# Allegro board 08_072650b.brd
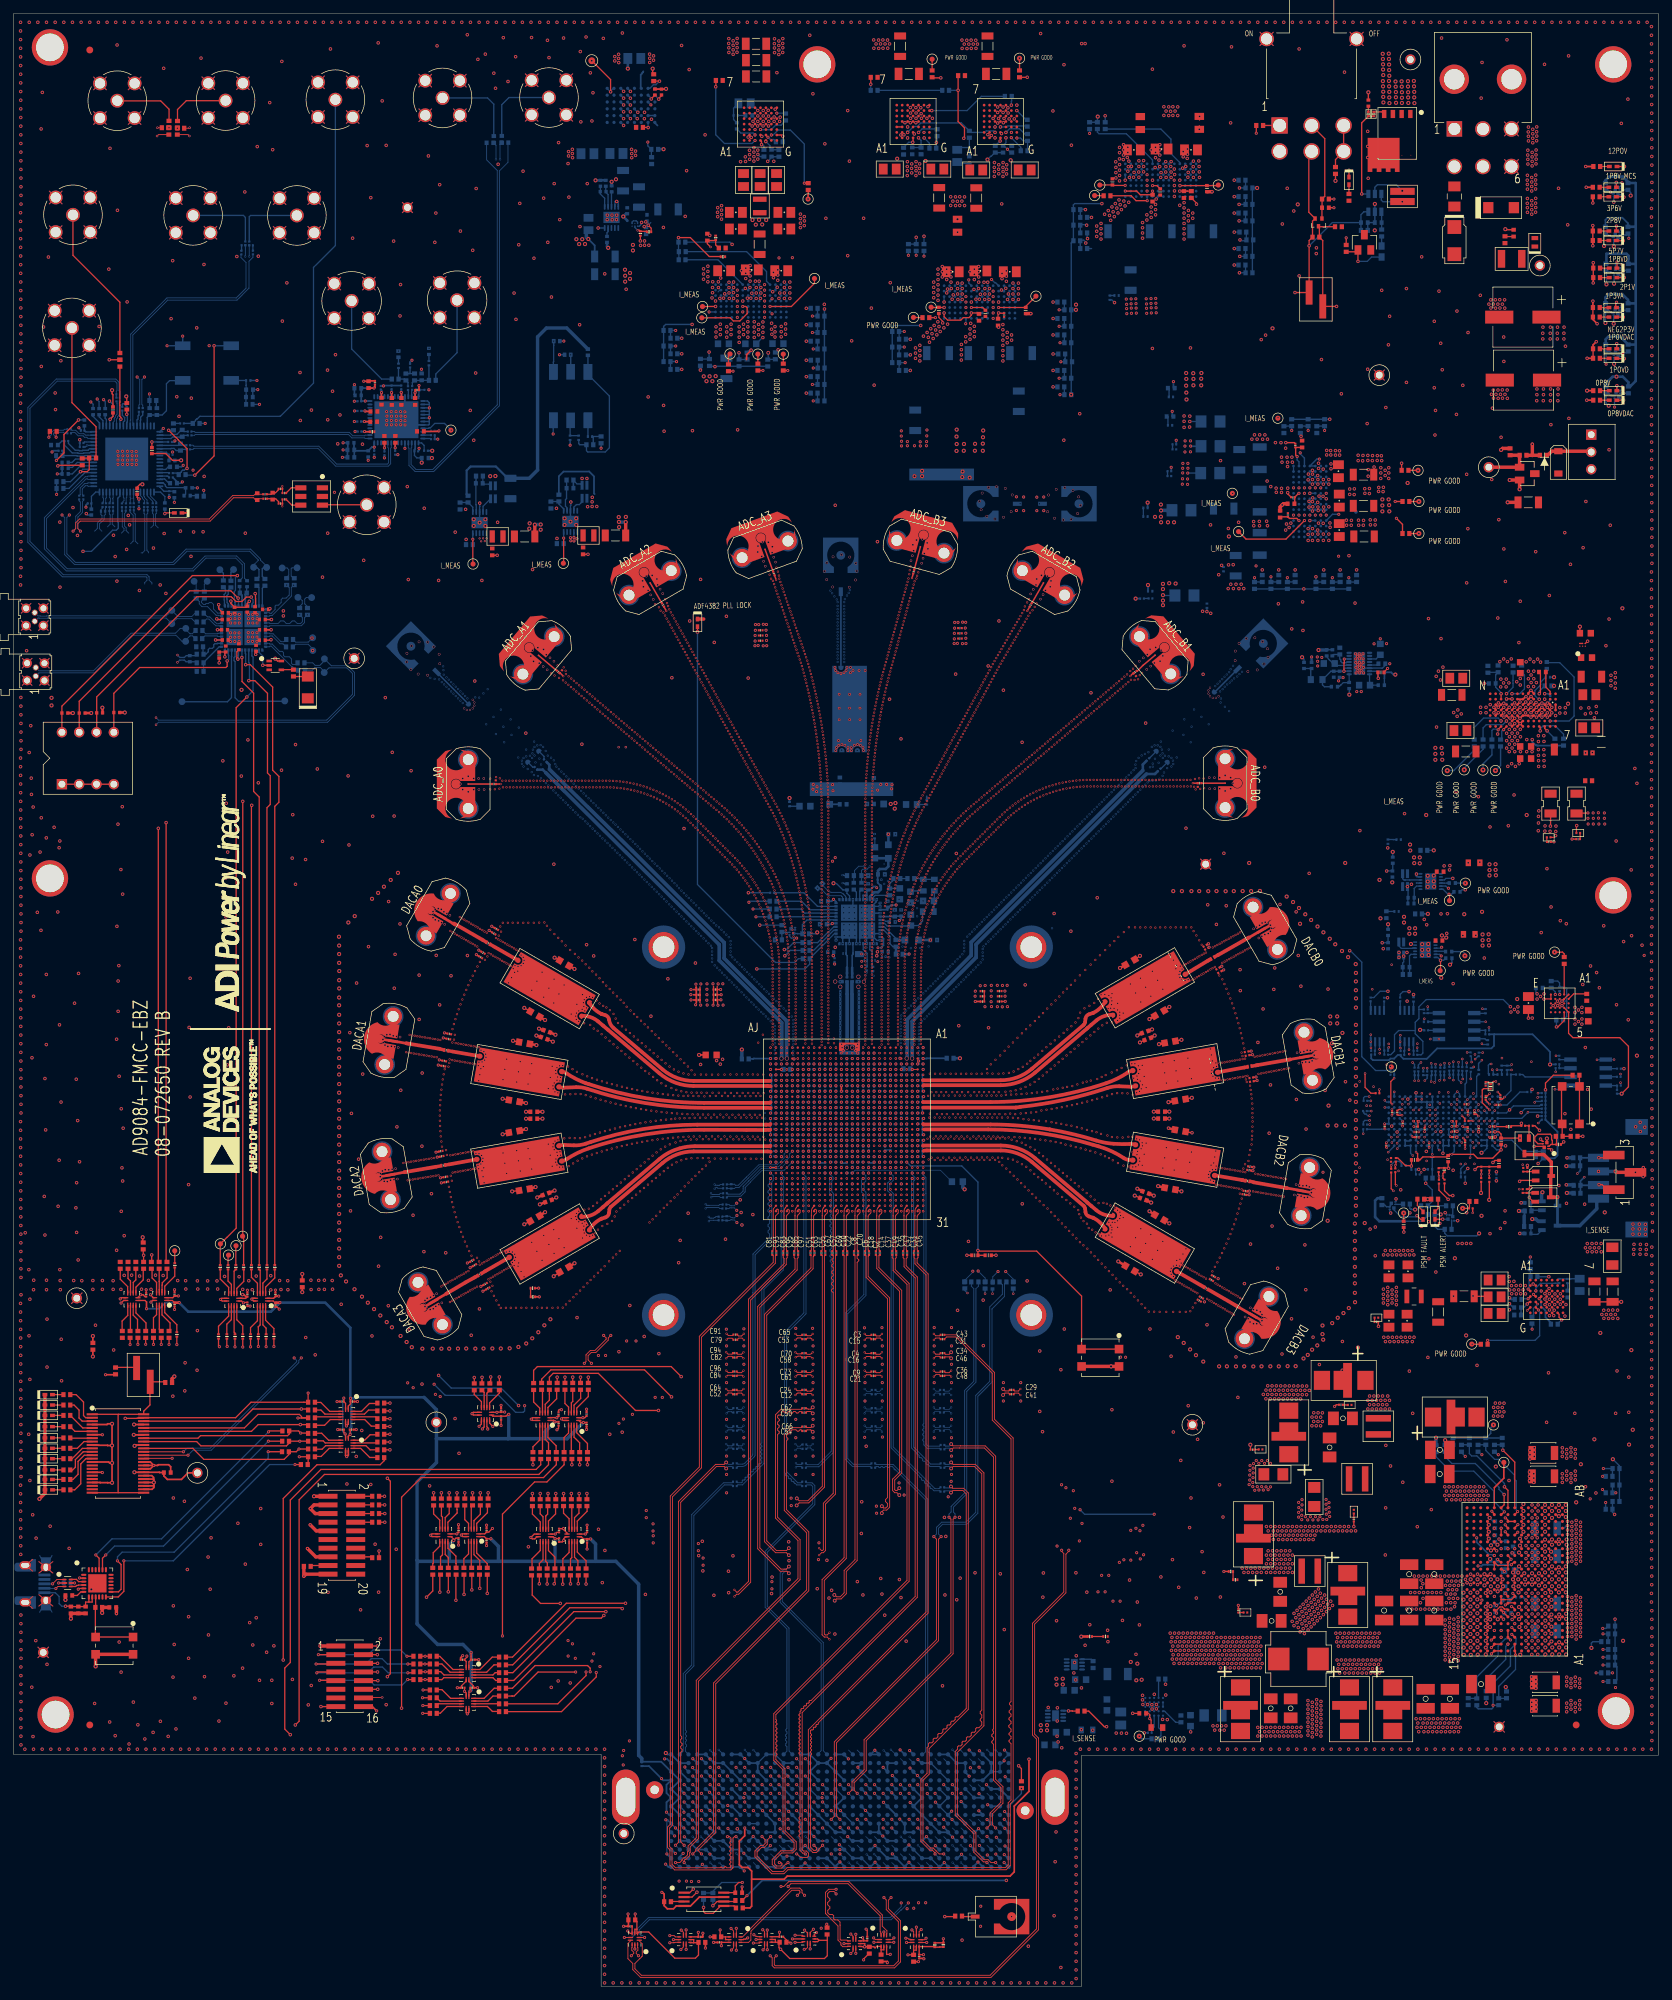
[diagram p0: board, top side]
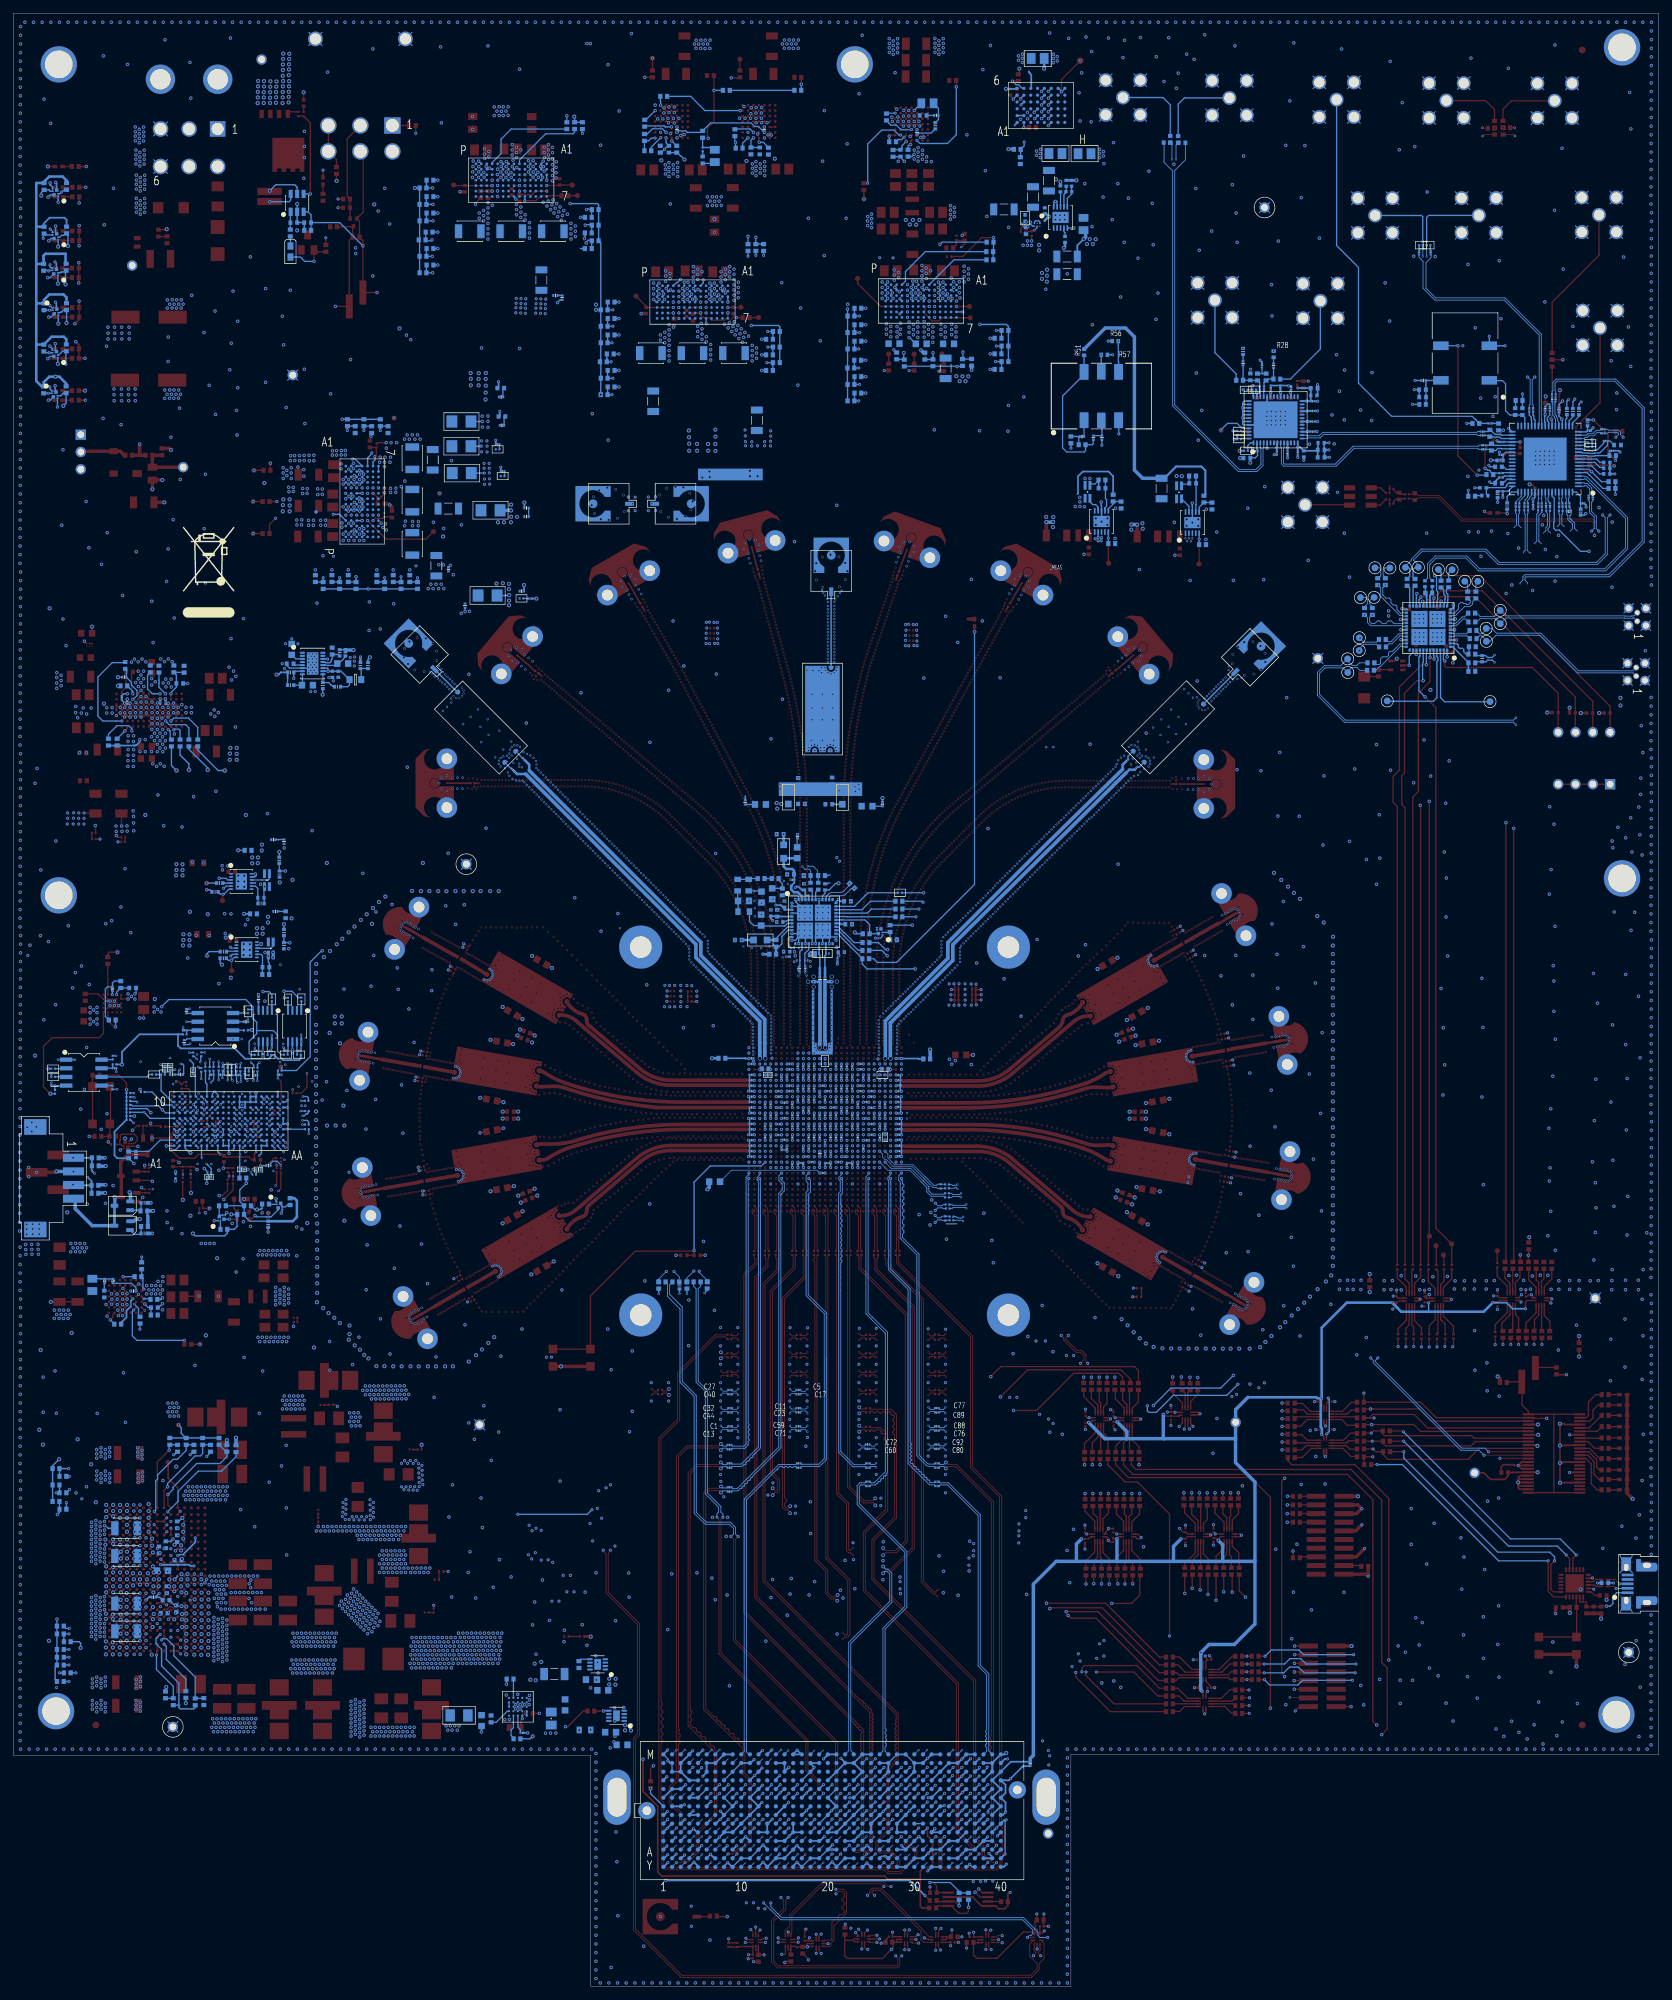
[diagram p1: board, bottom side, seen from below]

Outline 241.43 x 289.43 mm; copper layers: TOP, L2_GROUND, L3_SIGNAL, L4_GROUND, L5_MIXED, L6_GROUND, L7_POWER, L8_GROUND, L9_POWER, L10_GROUND, L11_POWER, L12_GROUND, L13_GROUND, L14_POWER, L15_GROUND, L16_POWER, L17_GROUND, L18_POWER, L19_GROUND, L20_POWER, L21_GROUND, L22_MIXED, L23_GROUND, L24_SIGNAL, L25_GROUND, BOTTOM. Coordinates in mm from the lower left corner of the outline.
Outline path: 0,289.43 0,34.04 86.23,34.04 86.23,0 156.72,0 156.72,33.91 241.43,33.91 241.43,289.43 0,289.43

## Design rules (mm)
constraint set DEFAULT: min track width 0.191
net group 4382_CLK_P_N: nets UNNAMED_9_CAP_I76_N2 UNNAMED_9_CAP_I78_N2
net group ADF4382_OUT: nets ADF4382_OUTN ADF4382_OUTP
net group ADS10_REFCLK: nets ADS10_REFCLK_N ADS10_REFCLK_P
net group AION_REFIN_N: nets AION_REFIN_N REFIN_DUT_N
net group AION_REFIN_P: nets AION_REFIN_P REFIN_DUT_P
net group APOLLO_SYSREF_N: nets APOLLO_SYSREF_N BSYNC5_N
net group APOLLO_SYSREF_P: nets APOLLO_SYSREF_P BSYNC5_P
net group ARTEMIS_REFIN: nets ARTEMIS_REFIN_N ARTEMIS_REFIN_P
net group ARTEMIS_SYNC: nets ARTEMIS_SYNC_N ARTEMIS_SYNC_P
net group BSYNC1_N: nets BSYNC1_N UNNAMED_52_CN2P4GNDV2_I39_N1
net group BSYNC1_P: nets BSYNC1_P UNNAMED_52_CN2P4GNDV2_I39_N2
net group BSYNC2_N: nets BSYNC2_N UNNAMED_52_CN2P4GNDV2_I35_N1
net group BSYNC2_P: nets BSYNC2_P UNNAMED_52_CN2P4GNDV2_I35_N2
net group BSYNC3_N: nets BSYNC3_N UNNAMED_52_NCTESTPAD_I168_N1
net group BSYNC3_P: nets BSYNC3_P UNNAMED_52_NCTESTPAD_I164_N1
net group BSYNC4_N: nets BSYNC4_N UNNAMED_52_NCTESTPAD_I177_N1
net group BSYNC4_P: nets BSYNC4_P UNNAMED_52_NCTESTPAD_I165_N1
net group BSYNC6_N: nets BSYNC6_N UNNAMED_52_NCTESTPAD_I170_N1
net group BSYNC6_P: nets BSYNC6_P UNNAMED_52_NCTESTPAD_I167_N1
net group BSYNC7_N: nets BSYNC7_N UNNAMED_52_NCTESTPAD_I176_N1
net group BSYNC7_P: nets BSYNC7_P UNNAMED_52_NCTESTPAD_I175_N1
net group CLKA: nets CLKA_N CLKA_P
net group CLKB: nets CLKB_N CLKB_P
net group CLKC: nets CLKC_N CLKC_P
net group DP1: nets UNNAMED_11_ADHMC7044_I155_CLKOUT0 UNNAMED_11_ADHMC7044_I155_CLKOUT0N
net group DP2: nets CLK_M2C_N_0 CLK_M2C_P_0
net group DP3: nets CLK_M2C_N_1 CLK_M2C_P_1
net group DP4: nets HSCI_CKO_N_FMC HSCI_CKO_P_FMC
net group DP5: nets HSCI_DIN_N_FMC HSCI_DIN_P_FMC
net group DP6: nets HSCI_DO_N_FMC HSCI_DO_P_FMC
net group DP7: nets SYNCINB_A0_N_FMC SYNCINB_A0_P_FMC
net group DP8: nets SYNCINB_A1_N_FMC SYNCINB_A1_P_FMC
net group DP9: nets SYNCINB_B0_N_FMC SYNCINB_B0_P_FMC
net group DP10: nets SYNCINB_B1_N_FMC SYNCINB_B1_P_FMC
net group DP11: nets SYSREF_A_N_FMC SYSREF_A_P_FMC
net group DP12: nets SYSREF_B_N_FMC SYSREF_B_P_FMC
net group DP13: nets SYSREF_N_FMC SYSREF_P_FMC
net group DP14: nets SYNCINB_A0_N_GPIO_FMC SYNCINB_A0_P_GPIO_FMC
net group DP15: nets SYNCINB_A1_N_GPIO_FMC SYNCINB_A1_P_GPIO_FMC
net group DP16: nets SYNCOUTB_A0_N_FMC SYNCOUTB_A0_P_FMC
net group DP17: nets SYNCOUTB_A1_N_FMC SYNCOUTB_A1_P_FMC
net group DP18: nets SYNCOUTB_B0_N_FMC SYNCOUTB_B0_P_FMC
net group DP19: nets SYNCOUTB_B1_N_FMC SYNCOUTB_B1_P_FMC
net group DP20: nets SYNCINB_B0_N_GPIO_FMC SYNCINB_B0_P_GPIO_FMC
net group DP21: nets SYNCOUTB_A0_N_GPIO_FMC SYNCOUTB_A0_P_GPIO_FMC
net group DP22: nets SYNCOUTB_A1_N_GPIO_FMC SYNCOUTB_A1_P_GPIO_FMC
net group DP23: nets SYNCINB_B1_N_GPIO_FMC SYNCINB_B1_P_GPIO_FMC
net group DP24: nets SYNCOUTB_B0_N_GPIO_FMC SYNCOUTB_B0_P_GPIO_FMC
net group DP25: nets SYNCOUTB_B1_N_GPIO_FMC SYNCOUTB_B1_P_GPIO_FMC
net group DP26: nets UNNAMED_36_CAP_I371_N1 UNNAMED_36_CAP_I372_N1
net group DP27: nets UNNAMED_11_ADHMC7044_I155_CLKOUT6 UNNAMED_11_ADHMC7044_I155_CLKOUT6N
net group FPGA_REFCLK_0: nets FPGA_REFCLK_0_N FPGA_REFCLK_0_P
net group FPGA_REFCLK_1: nets FPGA_REFCLK_1_N FPGA_REFCLK_1_P
net group FPGA_REFCLK_2: nets FPGA_REFCLK_2_N FPGA_REFCLK_2_P
net group FPGA_REFCLK_3: nets FPGA_REFCLK_3_N FPGA_REFCLK_3_P
net group FPGA_REFCLK_4: nets FPGA_REFCLK_4_N FPGA_REFCLK_4_P
net group FPGA_REFCLK_5: nets FPGA_REFCLK_5_N FPGA_REFCLK_5_P
net group HMC7044_CLK0: nets HMC7044_CLK0_N HMC7044_CLK0_P
net group HMC7044_CLK2: nets HMC7044_CLK2_N HMC7044_CLK2_P
net group HMC7044_CLK5: nets HMC7044_CLK5_N HMC7044_CLK5_P
net group HMC7044_CLK8: nets HMC7044_CLK8_N HMC7044_CLK8_P
net group HMC7044_CLK9: nets HMC7044_CLK9_N HMC7044_CLK9_P
net group HMC7044_CLK10: nets HMC7044_CLK10_N HMC7044_CLK10_P
net group HMC7044_CLK11: nets HMC7044_CLK11_N HMC7044_CLK11_P
net group HMC7044_CLK12: nets HMC7044_CLK12_N HMC7044_CLK12_P
net group HMC7044_CLK13: nets HMC7044_CLK13_N HMC7044_CLK13_P
net group HMC7044_FIN: nets HMC7044_FIN_N HMC7044_FIN_P
net group HMC7044_REFIN: nets HMC7044_REFIN_N HMC7044_REFIN_P
net group HSCI-CLKIN_P_N_FMC: nets HSCI_CKIN_N_FMC HSCI_CKIN_P_FMC
net group HSCI_CKIN: nets HSCI_CKIN_N HSCI_CKIN_P
net group HSCI_CKO: nets HSCI_CKO_N HSCI_CKO_P
net group HSCI_DIN: nets HSCI_DIN_N HSCI_DIN_P
net group HSCI_DO: nets HSCI_DO_N HSCI_DO_P
net group REFCLK: nets REFCLK_N REFCLK_P
net group RFOUT-N-P: nets UNNAMED_36_CAP_I396_N1 UNNAMED_36_CAP_I397_N1
net group SRXA_0: nets SRXA_0N SRXA_0P
net group SRXA_1: nets SRXA_1N SRXA_1P
net group SRXA_2: nets SRXA_2N SRXA_2P
net group SRXA_3: nets SRXA_3N SRXA_3P
net group SRXA_4: nets SRXA_4N SRXA_4P
net group SRXA_5: nets SRXA_5N SRXA_5P
net group SRXA_6: nets SRXA_6N SRXA_6P
net group SRXA_7: nets SRXA_7N SRXA_7P
net group SRXA_8: nets SRXA_8N SRXA_8P
net group SRXA_9: nets SRXA_9N SRXA_9P
net group SRXA_10: nets SRXA_10N SRXA_10P
net group SRXA_11: nets SRXA_11N SRXA_11P
net group SRXA_FMC_0: nets SRXA_0N_FMC SRXA_0P_FMC
net group SRXA_FMC_1: nets SRXA_1N_FMC SRXA_1P_FMC
net group SRXA_FMC_2: nets SRXA_2N_FMC SRXA_2P_FMC
net group SRXA_FMC_3: nets SRXA_3N_FMC SRXA_3P_FMC
net group SRXA_FMC_4: nets SRXA_4N_FMC SRXA_4P_FMC
net group SRXA_FMC_5: nets SRXA_5N_FMC SRXA_5P_FMC
net group SRXA_FMC_6: nets SRXA_6N_FMC SRXA_6P_FMC
net group SRXA_FMC_7: nets SRXA_7N_FMC SRXA_7P_FMC
net group SRXA_FMC_8: nets SRXA_8N_FMC SRXA_8P_FMC
net group SRXA_FMC_9: nets SRXA_9N_FMC SRXA_9P_FMC
net group SRXA_FMC_10: nets SRXA_10N_FMC SRXA_10P_FMC
net group SRXA_FMC_11: nets SRXA_11N_FMC SRXA_11P_FMC
net group SRXB_0: nets SRXB_0N SRXB_0P
net group SRXB_1: nets SRXB_1N SRXB_1P
net group SRXB_2: nets SRXB_2N SRXB_2P
net group SRXB_3: nets SRXB_3N SRXB_3P
net group SRXB_4: nets SRXB_4N SRXB_4P
net group SRXB_5: nets SRXB_5N SRXB_5P
net group SRXB_6: nets SRXB_6N SRXB_6P
net group SRXB_7: nets SRXB_7N SRXB_7P
net group SRXB_8: nets SRXB_8N SRXB_8P
net group SRXB_9: nets SRXB_9N SRXB_9P
net group SRXB_10: nets SRXB_10N SRXB_10P
net group SRXB_11: nets SRXB_11N SRXB_11P
net group SRXB_FMC_0: nets SRXB_0N_FMC SRXB_0P_FMC
net group SRXB_FMC_1: nets SRXB_1N_FMC SRXB_1P_FMC
net group SRXB_FMC_2: nets SRXB_2N_FMC SRXB_2P_FMC
net group SRXB_FMC_3: nets SRXB_3N_FMC SRXB_3P_FMC
net group SRXB_FMC_4: nets SRXB_4N_FMC SRXB_4P_FMC
net group SRXB_FMC_5: nets SRXB_5N_FMC SRXB_5P_FMC
net group SRXB_FMC_6: nets SRXB_6N_FMC SRXB_6P_FMC
net group SRXB_FMC_7: nets SRXB_7N_FMC SRXB_7P_FMC
net group SRXB_FMC_8: nets SRXB_8N_FMC SRXB_8P_FMC
net group SRXB_FMC_9: nets SRXB_9N_FMC SRXB_9P_FMC
net group SRXB_FMC_10: nets SRXB_10N_FMC SRXB_10P_FMC
net group SRXB_FMC_11: nets SRXB_11N_FMC SRXB_11P_FMC
net group STXA_0: nets STXA_0N STXA_0P
net group STXA_1: nets STXA_1N STXA_1P
net group STXA_2: nets STXA_2N STXA_2P
net group STXA_3: nets STXA_3N STXA_3P
net group STXA_4: nets STXA_4N STXA_4P
net group STXA_5: nets STXA_5N STXA_5P
net group STXA_6: nets STXA_6N STXA_6P
net group STXA_7: nets STXA_7N STXA_7P
net group STXA_8: nets STXA_8N STXA_8P
net group STXA_9: nets STXA_9N STXA_9P
net group STXA_10: nets STXA_10N STXA_10P
net group STXA_11: nets STXA_11N STXA_11P
net group STXA_FMC_0: nets STXA_0N_FMC STXA_0P_FMC
net group STXA_FMC_1: nets STXA_1N_FMC STXA_1P_FMC
net group STXA_FMC_2: nets STXA_2N_FMC STXA_2P_FMC
net group STXA_FMC_3: nets STXA_3N_FMC STXA_3P_FMC
net group STXA_FMC_4: nets STXA_4N_FMC STXA_4P_FMC
net group STXA_FMC_5: nets STXA_5N_FMC STXA_5P_FMC
net group STXA_FMC_6: nets STXA_6N_FMC STXA_6P_FMC
net group STXA_FMC_7: nets STXA_7N_FMC STXA_7P_FMC
net group STXA_FMC_8: nets STXA_8N_FMC STXA_8P_FMC
net group STXA_FMC_9: nets STXA_9N_FMC STXA_9P_FMC
net group STXA_FMC_10: nets STXA_10N_FMC STXA_10P_FMC
net group STXA_FMC_11: nets STXA_11N_FMC STXA_11P_FMC
net group STXB_0: nets STXB_0N STXB_0P
net group STXB_1: nets STXB_1N STXB_1P
net group STXB_2: nets STXB_2N STXB_2P
net group STXB_3: nets STXB_3N STXB_3P
net group STXB_4: nets STXB_4N STXB_4P
net group STXB_5: nets STXB_5N STXB_5P
net group STXB_6: nets STXB_6N STXB_6P
net group STXB_7: nets STXB_7N STXB_7P
net group STXB_8: nets STXB_8N STXB_8P
net group STXB_9: nets STXB_9N STXB_9P
net group STXB_10: nets STXB_10N STXB_10P
net group STXB_11: nets STXB_11N STXB_11P
net group STXB_FMC_0: nets STXB_0N_FMC STXB_0P_FMC
net group STXB_FMC_1: nets STXB_1N_FMC STXB_1P_FMC
net group STXB_FMC_2: nets STXB_2N_FMC STXB_2P_FMC
net group STXB_FMC_3: nets STXB_3N_FMC STXB_3P_FMC
net group STXB_FMC_4: nets STXB_4N_FMC STXB_4P_FMC
net group STXB_FMC_5: nets STXB_5N_FMC STXB_5P_FMC
net group STXB_FMC_6: nets STXB_6N_FMC STXB_6P_FMC
net group STXB_FMC_7: nets STXB_7N_FMC STXB_7P_FMC
net group STXB_FMC_8: nets STXB_8N_FMC STXB_8P_FMC
net group STXB_FMC_9: nets STXB_9N_FMC STXB_9P_FMC
net group STXB_FMC_10: nets STXB_10N_FMC STXB_10P_FMC
net group STXB_FMC_11: nets STXB_11N_FMC STXB_11P_FMC
net group SYNCINB_A0: nets SYNCINB_A0_N SYNCINB_A0_P
net group SYNCINB_A1: nets SYNCINB_A1_N SYNCINB_A1_P
net group SYNCINB_B0: nets SYNCINB_B0_N SYNCINB_B0_P
net group SYNCINB_B1: nets SYNCINB_B1_N SYNCINB_B1_P
net group SYNCOUTB_A0: nets SYNCOUTB_A0_N SYNCOUTB_A0_P
net group SYNCOUTB_A1: nets SYNCOUTB_A1_N SYNCOUTB_A1_P
net group SYNCOUTB_B0: nets SYNCOUTB_B0_N SYNCOUTB_B0_P
net group SYNCOUTB_B1: nets SYNCOUTB_B1_N SYNCOUTB_B1_P
net group SYSREF: nets SYSREF_N SYSREF_P
net group SYSREF_A: nets SYSREF_A_N SYSREF_A_P
net group SYSREF_B: nets SYSREF_B_N SYSREF_B_P
net group SYSREF_IN_N_FMC: nets BSYNC8_N SYSREF_IN_N_FMC
net group SYSREF_IN_P_FMC: nets BSYNC8_P SYSREF_IN_P_FMC
net group SYSREF_OUT_N_FMC: nets BSYNC9_N SYSREF_OUT_N_FMC
net group SYSREF_OUT_P_FMC: nets BSYNC9_P SYSREF_OUT_P_FMC
net group UNNAMED_29_ADF4382_I312_SYNC: nets UNNAMED_36_ADF4382_I312_SYNCN UNNAMED_36_ADF4382_I312_SYNCP
net group USB_D: nets USB_DN USB_DP
nets with their own width: min track width 0.108; nets UNNAMED_15_ADLTM4681_I3_PGOOD0 UNNAMED_41_ADLTM4709_I15_VO20 UNNAMED_41_ADLTM4709_I15_VO32
nets with their own width: min track width 0.133; nets UNNAMED_15_ADLTM4681_I3_PGOOD2
nets with their own width: min track width 0.178; nets DGND FMC_3P3V FMC_VADJ VDDD_1P8
nets with their own width: min track width 0.191; nets UNNAMED_15_ADLTM4681_I3_SDA01 VNEGM1P0_ADC

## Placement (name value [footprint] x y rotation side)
A1  LT1990IMS8-10#PBF  [MSOP8]  200.18 140.89 0 bottom
A2  LT1990IMS8-10#PBF  [MSOP8]  204.5 140.89 0 bottom
A3  LT1990HS8#PBF  [SO8NB-5]  211.81 140.89 90 bottom
A4  LT1990HS8#PBF  [SO8NB-5]  231.11 134.06 270 bottom
ADC_A0  SF1521-60070-1S  [CNAMPHENOLSF1521-60070-XS#2]  66.73 176.4 90 top
ADC_A1  SF1521-60070-1S  [CNAMPHENOLSF1521-60070-XS#2]  77.05 195.28 50 top
ADC_A2  SF1521-60070-1S  [CNAMPHENOLSF1521-60070-XS#2]  93.43 205.91 30 top
ADC_A3  SF1521-60070-1S  [CNAMPHENOLSF1521-60070-XS#2]  110.3 210.83 20 top
ADC_B0  SF1521-60070-1S  [CNAMPHENOLSF1521-60070-XS#2]  177.83 176.53 270 top
ADC_B1  SF1521-60070-1S  [CNAMPHENOLSF1521-60070-XS#2]  167.55 195.3 310 top
ADC_B2  SF1521-60070-1S  [CNAMPHENOLSF1521-60070-XS#2]  151.17 205.91 330 top
ADC_B3  SF1521-60070-1S  [CNAMPHENOLSF1521-60070-XS#2]  133.1 211.21 345 top
BUFDIS  TMM-102-01-G-S-SM  [CNSAMTECTMM-102-01-G-S-SM]  19.05 89.71 0 top
C1  0.1uF  [C0201]  136.27 82.17 180 bottom
C1WA  1uF  [C0603]  80.84 150.12 150 top
C1WB  1uF  [C0603]  168.2 142.78 30 top
C1XA  1uF  [C0603]  74.98 138.41 170 top
C1XB  1uF  [C0603]  169.75 138.55 10 top
C1YA  1uF  [C0603]  73.48 125.4 190 top
C1YB  1uF  [C0603]  171.24 125.54 350 top
C1ZA  1uF  [C0603]  76.52 112.66 210 top
C1ZB  1uF  [C0603]  168.2 112.8 330 top
C2  0.1uF  [C0201]  126.57 107.6 90 top
C2WA  1uF  [C0603]  76.52 142.64 150 top
C2WB  1uF  [C0603]  163.89 150.26 30 top
C2XA  1uF  [C0603]  73.48 129.91 170 top
C2XB  1uF  [C0603]  171.24 130.05 10 top
C2YA  1uF  [C0603]  74.98 116.89 190 top
C2YB  1uF  [C0603]  169.75 117.03 350 top
C2ZA  1uF  [C0603]  80.84 105.18 210 top
C2ZB  1uF  [C0603]  163.89 105.32 330 top
C3  0.1uF  [C0201]  126.19 95.59 180 top
C3WA  0.1uF  [C0201]  70.49 154.48 150 top
C3WB  0.1uF  [C0201]  174.9 152.68 30 top
C3XA  0.1uF  [C0201]  63.82 138.99 170 top
C3XB  0.1uF  [C0201]  181.67 133.3 10 top
C3YA  0.1uF  [C0201]  63.38 118.77 190 top
C3YB  0.1uF  [C0201]  181.34 119.75 350 top
C3ZA  0.1uF  [C0201]  69.23 103.06 210 top
C3ZB  0.1uF  [C0201]  175.82 103.63 330 top
C4  0.1uF  [C0201]  126.19 92.9 180 top
C4WA  0.1uF  [C0201]  70.87 155.14 150 top
C4WB  0.1uF  [C0201]  176.78 149.35 30 top
C4XA  0.1uF  [C0201]  63.95 139.74 170 top
C4XB  0.1uF  [C0201]  181.75 132.76 10 top
C4YA  0.1uF  [C0201]  62.83 121.78 190 top
C4YB  0.1uF  [C0201]  180.81 116.68 350 top
C4ZA  0.1uF  [C0201]  67.27 106.47 210 top
C4ZB  0.1uF  [C0201]  174.04 100.61 330 top
C5  0.1uF  [C0201]  126.24 87.5 180 bottom
C5WA  0.1uF  [C0201]  69.67 153.04 150 top
C5WB  0.1uF  [C0201]  176 150.88 30 top
C5XA  0.1uF  [C0201]  63.49 137.33 170 top
C5XB  0.1uF  [C0201]  181.43 134.98 10 top
C5YA  0.1uF  [C0201]  63.05 120.45 190 top
C5YB  0.1uF  [C0201]  181.13 118.16 350 top
C5ZA  0.1uF  [C0201]  68.42 104.44 210 top
C5ZB  0.1uF  [C0201]  175.05 102.4 330 top
C6  0.1uF  [C0201]  124.97 107.6 90 top
C6WA  0.1uF  [C0201]  68.53 150.99 150 top
C6WB  0.1uF  [C0201]  175.13 152.25 30 top
C6XA  0.1uF  [C0201]  63.08 135.02 170 top
C6XB  0.1uF  [C0201]  180.98 137.12 10 top
C6YA  0.1uF  [C0201]  62.69 122.53 190 top
C6YB  0.1uF  [C0201]  181.47 120.27 350 top
C6ZA  0.1uF  [C0201]  67.65 105.81 210 top
C6ZB  0.1uF  [C0201]  174.35 101.07 330 top
C7  0.1uF  [C0201]  126.19 76.74 180 bottom
C7WA  0.1uF  [C0201]  68.91 151.65 150 top
C7WB  0.1uF  [C0201]  177.06 148.82 30 top
C7XA  0.1uF  [C0201]  63.21 135.77 170 top
C7XB  0.1uF  [C0201]  181.12 136.58 10 top
C7YA  0.1uF  [C0201]  63.52 118.02 190 top
C7YB  0.1uF  [C0201]  180.64 116.18 350 top
C7ZA  0.1uF  [C0201]  69.61 102.4 210 top
C7ZB  0.1uF  [C0201]  176.12 104.19 330 top
C8  0.1uF  [C0201]  123.37 107.6 90 top
C9  0.1uF  [C0201]  126.19 90.21 180 top
C10  0.1uF  [C0201]  121.77 107.6 90 top
C11  0.1uF  [C0201]  126.24 84.84 180 bottom
C12  0.1uF  [C0201]  116.03 86.88 0 top
C13  0.1uF  [C0201]  136.27 81.53 180 bottom
C14  0.1uF  [C0201]  127.15 107.6 90 top
C15  0.1uF  [C0201]  126.19 94.96 180 top
C16  0.1uF  [C0201]  126.19 92.26 180 top
C17  0.1uF  [C0201]  126.24 86.87 180 bottom
C18  0.1uF  [C0201]  125.55 107.6 90 top
C19  0.1uF  [C0201]  126.19 76.1 180 bottom
C20  0.1uF  [C0201]  123.95 107.6 90 top
C21  0.1uF  [C0201]  126.19 89.57 180 top
C22  0.1uF  [C0201]  122.35 107.6 90 top
C23  0.1uF  [C0201]  126.24 84.2 180 bottom
C24  0.1uF  [C0201]  116.03 87.51 0 top
C25  0.1uF  [C0201]  136.35 76.74 180 bottom
C26  0.1uF  [C0201]  136.35 79.43 180 bottom
C27  0.1uF  [C0201]  136.27 87.5 180 bottom
C28  0.1uF  [C0201]  125.22 149.33 90 bottom
C29  0.1uF  [C0201]  146.51 87.51 180 top
C30  0.1uF  [C0201]  136.32 73.22 180 bottom
C31  0.1uF  [C0201]  136.35 94.96 180 top
C32  0.1uF  [C0201]  136.27 84.84 180 bottom
C33  0.1uF  [C0201]  132.17 107.6 90 top
C34  0.1uF  [C0201]  136.35 92.9 180 top
C35  0.1uF  [C0201]  130.57 107.6 90 top
C36  0.1uF  [C0201]  136.35 90.21 180 top
C37  0.1uF  [C0201]  128.97 107.6 90 top
C38  0.1uF  [C0201]  136.35 76.1 180 bottom
C39  0.1uF  [C0201]  136.35 78.79 180 bottom
C40  0.1uF  [C0201]  136.27 86.87 180 bottom
C41  0.1uF  [C0201]  146.51 86.88 180 top
C42  0.1uF  [C0201]  136.32 72.59 180 bottom
C43  0.1uF  [C0201]  136.35 95.59 180 top
C44  0.1uF  [C0201]  136.27 84.2 180 bottom
C45  0.1uF  [C0201]  132.75 107.6 90 top
C46  0.1uF  [C0201]  136.35 92.26 180 top
C47  0.1uF  [C0201]  131.15 107.6 90 top
C48  0.1uF  [C0201]  136.35 89.57 180 top
C49  0.1uF  [C0201]  129.55 107.6 90 top
C50  0.1uF  [C0201]  116.03 84.18 0 top
C51  0.1uF  [C0201]  116.97 107.6 90 top
C52  0.1uF  [C0201]  105.87 86.88 0 top
C53  0.1uF  [C0201]  116.03 94.96 0 top
C54  0.1uF  [C0201]  116.03 81.49 0 top
C55  0.1uF  [C0201]  118.57 107.6 90 top
C56  0.1uF  [C0201]  116.03 76.1 0 bottom
C57  0.1uF  [C0201]  120.17 107.6 90 top
C58  0.1uF  [C0201]  116.03 92.26 0 top
C59  0.1uF  [C0201]  126.24 82.17 180 bottom
C60  0.1uF  [C0201]  116.08 78.87 0 bottom
C61  0.1uF  [C0201]  116.03 89.57 0 top
C62  0.1uF  [C0201]  116.03 84.82 0 top
C63  0.1uF  [C0201]  117.55 107.6 90 top
C64  0.1uF  [C0201]  105.87 87.51 0 top
C65  0.1uF  [C0201]  116.03 95.59 0 top
C66  0.1uF  [C0201]  116.03 82.12 0 top
C67  0.1uF  [C0201]  119.15 107.6 90 top
C68  0.1uF  [C0201]  116.03 76.74 0 bottom
C69  0.1uF  [C0201]  120.75 107.6 90 top
C70  0.1uF  [C0201]  116.03 92.9 0 top
C71  0.1uF  [C0201]  126.24 81.53 180 bottom
C72  0.1uF  [C0201]  116.08 79.5 0 bottom
C73  0.1uF  [C0201]  116.03 90.21 0 top
C74  0.1uF  [C0201]  105.87 73.41 0 bottom
C75  0.1uF  [C0201]  105.87 76.1 0 bottom
C76  0.1uF  [C0201]  105.92 81.53 0 bottom
C77  0.1uF  [C0201]  105.92 84.84 0 bottom
C78  0.1uF  [C0201]  116.03 74.04 180 bottom
C79  0.1uF  [C0201]  105.93 94.87 0 top
C80  0.1uF  [C0201]  105.92 78.87 0 bottom
C81  0.1uF  [C0201]  111.37 107.6 90 top
C82  0.1uF  [C0201]  105.87 92.26 0 top
C83  0.1uF  [C0201]  112.97 107.6 90 top
C84  0.1uF  [C0201]  105.87 89.57 0 top
C85  0.1uF  [C0201]  114.57 107.6 90 top
C86  0.1uF  [C0201]  105.87 74.04 0 bottom
C87  0.1uF  [C0201]  105.87 76.74 0 bottom
C88  0.1uF  [C0201]  105.92 82.17 0 bottom
C89  0.1uF  [C0201]  105.92 84.2 0 bottom
C90  0.1uF  [C0201]  116.03 73.41 180 bottom
C91  0.1uF  [C0201]  105.93 95.63 0 top
C92  0.1uF  [C0201]  105.92 79.5 0 bottom
C93  0.1uF  [C0201]  111.95 107.6 90 top
C94  0.1uF  [C0201]  105.87 92.9 0 top
C95  0.1uF  [C0201]  113.55 107.6 90 top
C96  0.1uF  [C0201]  105.87 90.21 0 top
C97  0.1uF  [C0201]  115.15 107.6 90 top
C98  4.7uF  [C0402]  7.57 221.9 180 bottom
C99  4.7uF  [C0402]  7.57 222.74 180 bottom
C100  1uF  [C0402]  34.63 234.27 0 bottom
C101  4.7uF  [C0402]  7.57 223.58 180 bottom
C102  4.7uF  [C0402]  129.34 157.45 90 bottom
C103  1uF  [C0402]  5.99 226.14 180 bottom
C104  100pF  [C0402]  34.61 233.17 0 bottom
C105  0.1uF  [C0201]  115.9 133.38 270 bottom
C106  1uF  [C0201]  57.89 234.49 270 bottom
C107  4.7uF  [C0402]  23.47 222.94 0 bottom
C108  1uF  [C0402]  135.05 153.52 0 bottom
C109  1uF  [C0402]  128.96 156.16 0 bottom
C110  4.7uF  [C0402]  23.47 220.53 0 bottom
C111  1uF  [C0402]  128.91 169.04 0 bottom
C112  1uF  [C0402]  128.3 158.78 90 bottom
C113  0.1uF  [C0201]  127.1 162.36 180 bottom
C114  1uF  [C0402]  127.94 151.82 0 bottom
C115  1uF  [C0402]  124.46 161.42 270 bottom
C116  1uF  [C0402]  123.32 161.42 270 bottom
C117  1uF  [C0402]  119.94 151.74 180 bottom
C118  1uF  [C0402]  118.85 155.83 180 bottom
C119  1uF  [C0402]  122.33 161.32 90 bottom
C120  0.1uF  [C0201]  127.93 133.34 270 bottom
C121  1000pF  [C0201]  128.73 133.34 270 bottom
C122  1uF  [C0402]  119.02 159.21 180 bottom
C123  1uF  [C0402]  125.43 161.32 90 bottom
C124  0.1uF  [C0402]  7.85 59.21 180 bottom
C125  1uF  [C0402]  126.26 176.78 90 bottom
C126  160pF  [C0402H22#2]  25.72 219.86 0 bottom
C127  4700pF  [C0402]  25.47 218.72 0 bottom
C128  4700pF  [C0402]  19.96 231.05 90 bottom
C129  1uF  [C0402]  21.03 231.05 90 bottom
C130  1uF  [C0402]  121.28 176.86 90 bottom
C131  1uF  [C0402]  121.77 173.43 0 bottom
C132  1uF  [C0603]  156.62 45.01 0 bottom
C133  10uF  [C0402]  83.59 210.61 90 top
C134  4.7uF  [C0402]  81.66 219.8 180 bottom
C135  22UF  [C0805H60_SP]  83.79 219.28 270 bottom
C136  10uF  [C0402]  220.18 257.23 270 top
C137  47uF  [C0805H60]  104.29 251.71 0 top
C138  47uF  [C0805H60]  108.36 251.84 0 top
C139  47uF  [C0805H60]  112.67 251.71 0 top
C140  10uF  [C0402#2]  193.78 192.51 90 bottom
C141  0.1uF  [C0402]  106.43 13.74 0 top
C142  0.1uF  [C0402]  9.5 55.22 270 top
C143  1uF  [C0603]  153.8 37.29 0 bottom
C144  0.1uF  [C0402]  14.55 55.6 0 top
C145  0.1uF  [C0201]  217.93 129.34 180 top
C146  0.1uF  [C0201]  218.24 130.45 90 top
C147  0.1uF  [C0201]  216.08 130.38 90 top
C148  0.1uF  [C0201]  213.23 129.41 180 top
C149  0.1uF  [C0201]  214.43 128.24 270 top
C150  1uF  [C0603]  152.12 35.43 180 bottom
C151  0.1uF  [C0201]  213.46 128.17 90 top
C152  0.1uF  [C0201]  215.04 125.86 270 top
C153  10UF  [C1206]  162.05 45.82 180 bottom
C154  0.1uF  [C0201]  213.06 123.77 270 top
C155  0.1uF  [C0201]  25.83 228.12 180 bottom
C156  0.1uF  [C0201]  25.83 227.56 180 bottom
C157  1uF  [C0402]  145.24 269.54 90 bottom
C158  1uF  [C0402]  131.9 269.29 90 bottom
C159  10UF  [C1206]  144.22 280.59 180 top
C160  10UF  [C1206]  131.39 280.59 180 top
C161  100uF  [C0805H53]  141.3 266.5 180 top
C162  100uF  [C0805H53]  135.59 266.62 0 top
C163  1uF  [C0402]  111.25 268.96 90 bottom
C164  100uF  [C0805H53]  148.41 266.5 0 top
C165  100uF  [C0805H53]  128.6 266.62 180 top
C166  1uF  [C0603]  221.95 181.91 0 top
C167  1uF  [C0603]  221.95 180.14 0 top
C168  0.1uF  [C0201]  219.89 188.44 90 bottom
C169  1uF  [C0603]  154.94 43.43 180 bottom
C170  100uF  [C0805H53]  107.14 265.02 270 top
C171  1uF  [C0603]  221.16 193.47 270 top
C172  0.1uF  [C0201]  224.76 188.47 90 bottom
C173  0.1uF  [C0201]  225.55 189.05 90 bottom
C174  0.1uF  [C0201]  219.13 188.44 90 bottom
C175  1uF  [C0603]  231.14 142.39 90 top
C176  0.1uF  [C0201]  226.92 146.33 270 bottom
C177  47uF  [C0805H60]  222.35 144.27 90 top
C178  100uF  [C0805H53]  231.27 184.66 180 top
C179  47uF  [C0805H60]  231.29 189.51 180 top
C180  100uF  [C0805H53]  212.37 184.25 0 top
C181  47uF  [C0805H60]  137.85 251.56 0 top
C182  47uF  [C0805H60]  141.91 251.69 0 top
C183  47uF  [C0805H60]  146.23 251.56 0 top
C184  10uF  [C0603]  104.19 241 0 bottom
C185  10uF  [C0603]  108.2 241 0 bottom
C186  10uF  [C0603]  112.19 241.02 0 bottom
C187  47uF  [C0805H60]  194.46 222.3 270 top
C188  47uF  [C0805H60]  194.59 217.98 270 top
C189  47uF  [C0805H60]  194.59 213.66 270 top
C190  100uF  [C0805H53]  211.76 191.92 0 top
C191  1uF  [C0402]  220.76 99.59 0 bottom
C192  10UF  [C1206]  232.04 101.93 90 top
C193  10uF  [C0402]  209.22 153.44 180 top
C194  10uF  [C0402]  209.4 163.55 180 top
C195  4.7uF  [C0402]  204.39 149.53 0 bottom
C196  4.7uF  [C0402]  205.13 159.72 0 bottom
C197  22UF  [C0805H60_SP]  203.68 152.27 90 bottom
C198  22UF  [C0805H60_SP]  204.24 162.31 90 bottom
C199  22UF  [C1210H106]  224.92 63.14 180 bottom
C200  22UF  [C1210H106]  224.92 67.21 180 bottom
C201  1uF  [C0402]  125.78 173.48 180 bottom
C202  1000pF  [C0201]  119.12 130.14 270 bottom
C203  1000pF  [C0201]  119.92 130.14 270 bottom
C204  0.1uF  [C0201]  121.52 133.34 270 bottom
C205  1000pF  [C0201]  122.32 133.34 270 bottom
C206  0.1uF  [C0201]  123.12 133.34 270 bottom
C207  1000pF  [C0201]  116.72 133.34 270 bottom
C208  0.1uF  [C0201]  34.44 235.61 0 bottom
C209  0.1uF  [C0201]  217.04 126.16 180 top
C210  0.1uF  [C0201]  217.02 125.35 180 top
C211  0.1uF  [C0201]  217.02 124.54 180 top
C212  0.1uF  [C0201]  7.74 226.73 180 bottom
C213  0.1uF  [C0201]  24.71 229.31 180 bottom
C214  0.1uF  [C0201]  23.09 222.02 180 bottom
C215  0.1uF  [C0201]  23.09 221.39 180 bottom
C216  0.1uF  [C0201]  25.63 226.11 180 bottom
C217  0.1uF  [C0201]  25.63 225.5 180 bottom
C218  0.1uF  [C0201]  6.86 225.3 0 bottom
C219  0.1uF  [C0201]  10.13 228.24 0 bottom
C220  0.1uF  [C0201]  14.58 231.29 270 bottom
C221  0.1uF  [C0201]  16.61 231.5 270 bottom
C222  1uF  [C0402]  10.57 55.22 270 top
C223  0.1uF  [C0201]  22.96 226.59 180 bottom
C224  0.01uF  [C0402]  8.41 55.22 270 top
C225  1uF  [C0402]  8.1 57.35 180 top
C226  0.1uF  [C0201]  23.06 224.71 180 bottom
C227  0.1uF  [C0201]  11.15 217.58 180 bottom
C228  0.1uF  [C0201]  18.39 217.45 270 bottom
C229  0.1uF  [C0201]  22.83 219.1 270 bottom
C230  0.1uF  [C0201]  10.24 218.44 270 bottom
C231  0.1uF  [C0201]  9.63 218.44 270 bottom
C232  0.1uF  [C0201]  33.43 254.38 90 bottom
C233  0.1uF  [C0201]  35.13 254.38 90 bottom
C234  0.1uF  [C0201]  166.78 37.21 0 bottom
C235  1uF  [C0603]  172.75 38.99 90 bottom
C236  47uF  [C0805H60]  162.51 39.29 90 bottom
C237  0.1uF  [C0201]  160.27 51.33 0 top
C238  22UF  [C1210H106]  182.91 224.21 270 bottom
C239  22UF  [C1210H106]  182.91 217.98 270 bottom
C240  22UF  [C1210H106]  182.91 211.63 270 bottom
C241  33pF  [C0603]  134.29 159.26 180 bottom
C242  20pF  [C0603]  131.7 156.44 90 bottom
C243  1000pF  [C0603]  131.65 159.82 270 bottom
C244  0.1uF  [C0402]  194.64 192.51 270 bottom
C245  1uF  [C0603]  200.61 196.16 90 bottom
C246  0.1uF  [C0402]  200.84 194.06 0 bottom
C247  1uF  [C0603]  198.3 190.91 180 bottom
C248  1uF  [C0603]  193.12 194.08 180 bottom
C249  22UF  [C1210H106]  135.69 239.62 0 bottom
C250  0.1uF  [C0201]  100.77 7.26 0 top
C251  0.1uF  [C0201]  132.92 4.38 270 top
C252  10pF  [C0603]  130.07 160.3 270 bottom
C253  1uF  [C0402]  127.38 163.14 180 bottom
C254  0.1uF  [C0201]  90.49 8.81 180 top
C255  10pF  [C0201]  127.74 151.08 180 bottom
C256  0.1uF  [C0201]  103.62 6.45 180 top
C257  0.1uF  [C0201]  135.2 6.07 90 top
C258  0.1uF  [C0201]  136.47 6.1 90 top
C259  10pF  [C0201]  120.51 150.57 90 bottom
C260  0.1uF  [C0201]  112.69 7.29 0 top
C261  0.1uF  [C0201]  125.3 7.01 90 top
C262  22UF  [C1210H106]  141.78 239.62 0 bottom
C263  22UF  [C1210H106]  147.88 239.62 0 bottom
C264  22UF  [C1210H106]  224.79 44.6 180 top
C265  0.1uF  [C0201]  65.9 47.93 0 top
C266  0.1uF  [C0201]  48.19 85.8 0 top
C267  0.1uF  [C0201]  84.18 66.89 270 top
C268  0.1uF  [C0201]  69.42 66.92 270 top
C269  0.1uF  [C0201]  67.42 47.93 0 top
C270  0.1uF  [C0201]  49.72 85.8 0 top
C271  0.1uF  [C0201]  84.18 65.37 270 top
C272  0.1uF  [C0201]  69.42 65.4 270 top
C273  0.1uF  [C0201]  84.1 83.96 270 top
C274  0.1uF  [C0201]  38.43 101.49 270 top
C275  0.1uF  [C0201]  23.62 101.57 270 top
C276  0.1uF  [C0201]  84.1 82.44 270 top
C277  0.1uF  [C0201]  38.43 99.97 270 top
C278  0.1uF  [C0201]  23.62 100.04 270 top
C279  0.01uF  [C0201]  50.72 229.59 180 bottom
C280  1uF  [C0402]  56.03 226.97 90 top
C281  0.01uF  [C0201]  59.23 234.21 0 top
C282  1uF  [C0402]  52.86 229.57 0 top
C283  0.01uF  [C0201]  59.11 225.22 0 bottom
C284  1uF  [C0402]  52.88 231.06 0 top
C285  0.01uF  [C0201]  53.9 234.54 90 bottom
C286  1uF  [C0402]  50.52 234.47 180 bottom
C287  1uF  [C0402]  49.5 226.47 180 bottom
C288  0.01uF  [C0201]  52.63 228.09 0 top
C289  1uF  [C0402]  50.57 233.43 180 bottom
C290  0.1uF  [C0402]  49.5 225.43 180 bottom
C291  0.01uF  [C0201]  55.47 234.59 90 bottom
C292  1uF  [C0402]  54 232.56 270 top
C293  1000pF  [C0402]  49.5 224.33 180 bottom
C294  0.01uF  [C0201]  50.77 228.12 180 bottom
C295  1uF  [C0402]  58.93 232.54 270 top
C296  0.01uF  [C0201]  56.01 224.99 270 bottom
C297  1uF  [C0402]  52.04 224.84 270 bottom
C298  0.01uF  [C0201]  54.43 224.92 270 bottom
C299  1uF  [C0402]  56.92 232.54 270 top
C300  0.01uF  [C0201]  52.93 225.02 270 bottom
C301  1uF  [C0402]  54.43 226.97 90 top
C302  0.01uF  [C0201]  56.9 234.59 90 bottom
C303  1uF  [C0402]  59.72 228.14 180 top
C304  0.01uF  [C0201]  50.75 231.14 180 bottom
C305  1uF  [C0402]  60.4 224.23 0 bottom
C306  0.01uF  [C0201]  50.75 232.56 180 bottom
C307  1uF  [C0402]  52.1 235 90 top
C308  0.01uF  [C0201]  53.04 235.28 90 top
C309  1uF  [C0402]  55.5 232.54 270 top
C310  1uF  [C0402]  130.28 157.48 90 bottom
C311  1uF  [C0402]  69.93 270.48 0 bottom
C312  1uF  [C0402]  70.48 270.97 270 bottom
C313  1uF  [C0402]  71.65 270.99 270 bottom
C314  1uF  [C0402]  72.11 270.51 180 bottom
C315  1uF  [C0201]  58.5 234.52 270 bottom
C316  0.1uF  [C0201]  58.19 237.79 270 bottom
C317  0.1uF  [C0201]  126.14 149.28 90 bottom
C318  1.5pF  [C0402]  35.76 218.57 270 top
C319  1.5pF  [C0402]  38.02 218.64 270 top
C320  1uF  [C0402]  185.9 216 270 top
C321  1uF  [C0402]  189.13 226.29 270 top
C322  1uF  [C0402]  59.89 236.14 270 bottom
C323  0.1uF  [C0201]  122.33 147.73 270 bottom
C324  0.1uF  [C0201]  121.95 147.4 180 bottom
C325  0.1uF  [C0201]  123.09 147.73 270 bottom
C326  0.1uF  [C0201]  168.13 178.47 45 bottom
C327  0.1uF  [C0201]  166.48 180 45 bottom
C328  0.1uF  [C0201]  78.04 179.82 135 bottom
C329  0.1uF  [C0201]  76.67 178.7 135 bottom
C330  0.1uF  [C0201]  123.47 147.4 0 bottom
C331  0.1uF  [C0201]  39.17 217.55 0 top
C332  0.1uF  [C0201]  39.73 218.16 0 top
C333  0.1uF  [C0201]  39.17 219.71 0 top
C334  0.1uF  [C0201]  39.73 219.1 0 top
C335  0.1uF  [C0201]  111.51 130.53 0 bottom
C336  0.1uF  [C0402]  77.88 139.11 340 top
C337  0.1uF  [C0201]  118.32 131.74 270 bottom
C338  0.1uF  [C0201]  111.38 126.52 0 bottom
C339  0.1uF  [C0402]  78.26 140.13 340 top
C340  0.1uF  [C0201]  111.53 131.34 0 bottom
C341  1000PF  [C0402]  76.36 127.3 0 top
C342  1000pF  [C0201]  119.12 131.74 270 bottom
C343  0.1uF  [C0201]  111.38 125.78 0 bottom
C344  1000PF  [C0402]  76.36 128.32 0 top
C345  0.1uF  [C0201]  111.53 133.71 0 bottom
C346  0.1uF  [C0402]  78.5 115.22 20 top
C347  1000pF  [C0201]  119.92 131.74 270 bottom
C348  0.1uF  [C0201]  111.51 129.03 0 bottom
C349  0.1uF  [C0402]  78.13 116.25 20 top
C350  0.1uF  [C0201]  115.49 128.93 0 bottom
C351  0.1uF  [C0201]  120.72 131.74 270 bottom
C352  0.1uF  [C0201]  111.38 122.55 0 bottom
C353  0.1uF  [C0201]  129.08 128.93 180 bottom
C354  0.1uF  [C0201]  123.93 131.74 270 bottom
C355  0.1uF  [C0201]  111.38 123.34 0 bottom
C356  0.1uF  [C0402]  201.5 157.23 270 bottom
C357  0.1uF  [C0402]  166.47 139 200 top
C358  0.1uF  [C0201]  129.11 124.92 180 bottom
C359  1000pF  [C0201]  124.73 131.74 270 bottom
C360  0.1uF  [C0201]  114.27 124.56 270 bottom
C361  0.1uF  [C0402]  166.09 140.02 200 top
C362  1000PF  [C0402]  168.5 127.32 180 top
C363  0.1uF  [C0201]  115.52 124.94 0 bottom
C364  1000pF  [C0201]  125.53 131.74 270 bottom
C365  0.1uF  [C0201]  114.27 126.16 270 bottom
C366  1000PF  [C0402]  168.5 128.34 180 top
C367  0.1uF  [C0402]  165.81 115.5 160 top
C368  0.1uF  [C0201]  115.52 126.52 0 bottom
C369  0.1uF  [C0201]  126.33 131.74 270 bottom
C370  0.1uF  [C0201]  130.3 126.11 270 bottom
C371  0.1uF  [C0201]  120.72 127.74 90 bottom
C372  1000pF  [C0201]  123.12 124.54 90 bottom
C373  0.1uF  [C0201]  120.72 126.14 90 bottom
C374  0.1uF  [C0201]  123.93 124.54 90 bottom
C375  0.1uF  [C0201]  133.13 133.74 180 bottom
C376  1000pF  [C0201]  121.52 127.74 90 bottom
C377  1000pF  [C0201]  121.52 124.54 90 bottom
C378  0.1uF  [C0201]  133.13 132.94 180 bottom
C379  0.1uF  [C0201]  122.32 127.74 90 bottom
C380  0.1uF  [C0201]  124.73 124.54 90 bottom
C381  0.1uF  [C0201]  133.13 131.34 180 bottom
C382  0.1uF  [C0201]  133.13 132.14 180 bottom
C383  1000pF  [C0201]  123.12 127.74 90 bottom
C384  0.1uF  [C0201]  120.72 124.54 90 bottom
C385  0.1uF  [C0201]  133.13 130.54 180 bottom
C386  0.1uF  [C0201]  133.13 129.74 180 bottom
C387  0.1uF  [C0201]  123.93 127.74 90 bottom
C388  0.1uF  [C0201]  125.53 122.94 270 bottom
C389  0.1uF  [C0201]  133.13 128.14 180 bottom
C390  0.1uF  [C0201]  133.13 128.94 180 bottom
C391  0.1uF  [C0201]  121.52 126.14 90 bottom
C392  1000pF  [C0201]  119.92 122.94 270 bottom
C393  0.1uF  [C0201]  133.13 127.34 180 bottom
C394  0.1uF  [C0201]  133.13 126.54 180 bottom
C395  0.1uF  [C0201]  123.12 126.14 90 bottom
C396  0.1uF  [C0201]  119.52 121.74 0 bottom
C397  0.1uF  [C0201]  133.13 124.94 180 bottom
C398  0.1uF  [C0201]  133.13 125.74 180 bottom
C399  1000pF  [C0201]  119.92 126.14 90 bottom
C400  1000pF  [C0201]  124.73 122.94 270 bottom
C401  0.1uF  [C0201]  133.13 124.14 180 bottom
C402  0.1uF  [C0201]  133.13 123.34 180 bottom
C403  0.1uF  [C0201]  123.93 126.14 90 bottom
C404  0.1uF  [C0201]  125.13 121.74 180 bottom
C405  0.1uF  [C0201]  133.13 121.74 180 bottom
C406  0.1uF  [C0201]  133.13 122.54 180 bottom
C407  1000pF  [C0201]  122.32 126.14 90 bottom
C408  0.1uF  [C0201]  119.12 122.94 270 bottom
C409  0.1uF  [C0201]  119.92 124.54 90 bottom
C410  1000pF  [C0201]  124.73 126.14 90 bottom
C411  0.1uF  [C0201]  117.12 131.34 180 bottom
C412  0.1uF  [C0201]  121.92 131.34 0 bottom
C413  0.1uF  [C0201]  117.12 132.14 180 bottom
C414  0.1uF  [C0201]  127.53 132.14 0 bottom
C415  0.1uF  [C0201]  122.72 132.14 180 bottom
C416  0.1uF  [C0201]  127.53 131.34 0 bottom
C417  1000pF  [C0201]  123.12 130.94 270 bottom
C418  0.1uF  [C0201]  115.11 127.69 90 bottom
C419  0.1uF  [C0201]  111.51 129.74 0 bottom
C420  0.1uF  [C0201]  111.53 132.94 0 bottom
C421  0.1uF  [C0201]  111.46 132.18 0 bottom
C422  0.1uF  [C0201]  130.3 124.51 270 bottom
C423  0.1uF  [C0201]  114.33 127.74 90 bottom
C424  0.1uF  [C0201]  114.3 129.31 90 bottom
C425  0.1uF  [C0201]  129.49 127.74 90 bottom
C426  1000pF  [C0201]  130.3 127.76 90 bottom
C427  1000pF  [C0201]  130.3 129.36 90 bottom
C428  0.1uF  [C0201]  122.72 119.34 180 bottom
C429  1uF  [C0603]  138.53 118.06 0 bottom
C430  0.1uF  [C0201]  129.18 130.54 0 bottom
C431  0.1uF  [C0201]  127.13 120.54 270 bottom
C432  0.1uF  [C0201]  122.32 130.14 90 bottom
C433  0.1uF  [C0201]  115.47 130.54 180 bottom
C434  0.1uF  [C0201]  126.33 120.54 270 bottom
C435  1uF  [C0603]  102.39 136.65 180 top
C436  10UF  [C0402]  169.75 230.33 0 bottom
C437  1000pF  [C0201]  125.53 120.54 270 bottom
C438  0.1uF  [C0201]  118.32 127.74 270 bottom
C439  10UF  [C0402]  169.93 234.49 0 bottom
C440  0.1uF  [C0201]  117.53 120.55 270 bottom
C441  0.1uF  [C0201]  118.32 126.14 90 bottom
C442  0.1uF  [C0201]  119.12 128.54 270 bottom
C443  0.1uF  [C0201]  129.13 131.34 0 bottom
C444  0.1uF  [C0201]  118.32 120.54 270 bottom
C445  0.1uF  [C0201]  126.33 127.74 270 bottom
C446  1000pF  [C0201]  119.92 128.54 270 bottom
C447  0.1uF  [C0201]  133.13 135.35 180 bottom
C448  0.1uF  [C0201]  115.52 131.34 180 bottom
C449  1000pF  [C0201]  119.12 120.54 270 bottom
C450  0.1uF  [C0201]  126.33 126.14 90 bottom
C451  0.1uF  [C0201]  124.73 128.54 270 bottom
C452  0.1uF  [C0201]  166.83 204.7 180 bottom
C453  0.1uF  [C0201]  122.32 123.74 270 bottom
C454  0.1uF  [C0201]  127.93 122.94 270 bottom
C455  1000pF  [C0201]  125.53 128.54 270 bottom
C456  0.1uF  [C0201]  128.7 122.99 270 bottom
C457  0.1uF  [C0201]  121.49 122.12 90 bottom
C458  0.1uF  [C0201]  120.32 120.94 180 bottom
C459  0.1uF  [C0201]  121.12 128.94 0 bottom
C460  0.1uF  [C0201]  121.52 120.54 270 bottom
C461  0.1uF  [C0201]  122.72 128.94 0 bottom
C462  0.1uF  [C0201]  111.46 136.14 0 bottom
C463  0.1uF  [C0201]  133.13 136.15 180 bottom
C464  0.1uF  [C0201]  131.13 129.34 90 bottom
C465  0.1uF  [C0201]  113.52 129.34 90 bottom
C466  0.1uF  [C0201]  123.12 120.54 270 bottom
C467  0.1uF  [C0201]  122.3 122.12 90 bottom
C468  0.1uF  [C0201]  131.13 127.74 90 bottom
C469  0.1uF  [C0201]  113.52 127.74 90 bottom
C470  0.1uF  [C0201]  124.33 120.94 0 bottom
C471  0.1uF  [C0201]  116.7 122.95 270 bottom
C472  1000pF  [C0201]  131.13 126.14 270 bottom
C473  1000pF  [C0201]  113.51 124.59 270 bottom
C474  0.1uF  [C0201]  122.3 120.52 270 bottom
C475  0.1uF  [C0201]  131.13 124.54 270 bottom
C476  0.1uF  [C0201]  113.49 126.16 270 bottom
C477  0.1uF  [C0201]  123.09 122.15 90 bottom
C478  0.1uF  [C0201]  118.32 130.14 270 bottom
C479  0.1uF  [C0201]  118.32 133.34 270 bottom
C480  0.1uF  [C0201]  118.32 134.95 90 bottom
C481  0.1uF  [C0201]  117.52 129.34 90 bottom
C482  1000pF  [C0201]  117.12 134.55 180 bottom
C483  1000pF  [C0201]  119.12 133.34 270 bottom
C484  1000pF  [C0201]  119.12 134.95 90 bottom
C485  0.1uF  [C0201]  117.52 127.74 90 bottom
C486  1000pF  [C0201]  119.92 133.34 270 bottom
C487  1000pF  [C0201]  119.92 134.95 90 bottom
C488  1000pF  [C0201]  117.52 126.14 270 bottom
C489  1000pF  [C0201]  117.12 135.35 180 bottom
C490  0.1uF  [C0201]  120.72 130.14 270 bottom
C491  0.1uF  [C0201]  120.72 133.34 270 bottom
C492  0.1uF  [C0201]  120.72 134.95 90 bottom
C493  0.1uF  [C0201]  117.52 124.54 270 bottom
C494  0.1uF  [C0201]  123.93 130.14 270 bottom
C495  0.1uF  [C0201]  123.93 133.34 270 bottom
C496  0.1uF  [C0201]  123.93 134.95 90 bottom
C497  0.1uF  [C0201]  127.13 129.34 90 bottom
C498  1000pF  [C0201]  127.53 134.55 0 bottom
C499  1000pF  [C0201]  124.73 130.14 270 bottom
C500  1000pF  [C0201]  124.73 133.34 270 bottom
C501  1000pF  [C0201]  124.73 134.95 90 bottom
C502  0.1uF  [C0201]  127.13 127.74 90 bottom
C503  1000pF  [C0201]  127.53 135.35 0 bottom
C504  1000pF  [C0201]  125.53 130.14 270 bottom
C505  1000pF  [C0201]  125.53 133.34 270 bottom
C506  1000pF  [C0201]  125.53 134.95 90 bottom
C507  1000pF  [C0201]  127.13 126.14 270 bottom
C508  0.1uF  [C0201]  126.33 130.14 270 bottom
C509  0.1uF  [C0201]  126.33 133.34 270 bottom
C510  0.1uF  [C0201]  126.33 134.95 90 bottom
C511  0.1uF  [C0201]  127.13 124.54 270 bottom
C512  22UF  [C1210H106]  224.54 78.26 180 top
C513  22UF  [C1210H106]  224.79 41.17 180 top
C514  22UF  [C1210H106]  224.54 74.83 180 top
C515  22UF  [C1210H106]  224.92 56.16 180 bottom
C516  22UF  [C1210H106]  224.92 52.1 180 bottom
C517  1uF  [C0402]  219.05 56.67 180 bottom
C518  2200pF  [C0402]  217.55 55.4 270 bottom
C519  150pF  [C0402]  219.33 54.76 180 bottom
C520  2200pF  [C0402]  220.09 64.03 90 bottom
C521  150pF  [C0402]  219.07 64.8 270 bottom
C522  0.1uF  [C0201]  199.54 137.26 0 bottom
C523  0.1uF  [C0201]  201.47 137.29 180 bottom
C524  10UF  [C1206]  108.99 280.21 180 top
C525  10UF  [C1206]  108.97 285.01 180 top
C526  0.1uF  [C0201]  203.86 137.24 0 bottom
C527  0.1uF  [C0201]  205.77 137.26 180 bottom
C528  100uF  [C0805H53]  111.99 265.02 270 top
C529  100uF  [C0805H53]  217.39 103.63 180 top
C530  0.1uF  [C0201]  216.31 140.26 180 bottom
C531  47uF  [C0805H60]  113.13 260.27 180 top
C532  0.1uF  [C0201]  95.32 202.67 120 top
C533  0.1uF  [C0201]  70.51 176.4 180 top
C534  47uF  [C0805H60]  113.13 257.84 180 top
C535  100uF  [C0805H53]  217.39 98.73 180 top
C536  0.1uF  [C0201]  164.63 192.83 40 top
C537  0.1uF  [C0201]  132.13 207.56 75 top
C538  0.1uF  [C0201]  235.64 132.16 180 bottom
C539  0.1uF  [C0201]  209.73 133.68 180 bottom
C540  0.1uF  [C0201]  207.49 133.96 90 bottom
C541  0.1uF  [C0201]  208.43 133.71 0 bottom
C542  0.1uF  [C0201]  211.05 133.76 0 bottom
C543  0.1uF  [C0201]  212.34 133.76 180 bottom
C544  0.1uF  [C0201]  207.11 125.68 90 top
C545  0.1uF  [C0201]  79.94 192.88 140 top
C546  0.1uF  [C0201]  111.6 207.3 110 top
C547  0.1uF  [C0201]  205.92 133.68 180 bottom
C548  0.1uF  [C0201]  203.1 128.2 90 top
C549  0.1uF  [C0201]  201.24 126.16 90 top
C550  0.1uF  [C0201]  203.89 126.57 90 top
C551  0.1uF  [C0201]  202.34 128.19 90 top
C552  0.1uF  [C0201]  202.39 133.76 180 bottom
C553  4.7NF  [C0402]  228.12 101.57 90 bottom
C554  0.1uF  [C0201]  17.63 217.32 270 bottom
C555  0.1uF  [C0201]  17.12 217.32 270 bottom
C556  0.1uF  [C0201]  16.48 217.3 270 bottom
C557  0.1uF  [C0201]  15.9 217.3 270 bottom
C558  0.1uF  [C0201]  13.56 217.32 270 bottom
C559  0.1uF  [C0201]  13.06 217.32 270 bottom
C560  0.1uF  [C0201]  14.58 217.32 270 bottom
C561  0.1uF  [C0201]  14.07 217.32 270 bottom
C562  0.1uF  [C0201]  15.09 232.82 90 bottom
C563  0.1uF  [C0201]  15.6 232.82 90 bottom
C564  0.1uF  [C0201]  18.39 231.29 90 bottom
C565  0.1uF  [C0201]  18.95 231.29 90 bottom
C566  0.1uF  [C0201]  8.15 227.86 180 bottom
C567  0.1uF  [C0201]  8.15 228.45 180 bottom
C568  0.1uF  [C0201]  19.66 217.32 270 bottom
C569  0.1uF  [C0201]  19.15 217.32 270 bottom
C570  0.1uF  [C0201]  20.93 217.32 270 bottom
C571  0.1uF  [C0201]  20.42 217.32 270 bottom
C572  2200pF  [C0402]  217.42 65.68 90 bottom
C573  150pF  [C0402]  217.42 67.72 270 bottom
C574  4.7uF  [C0402]  218.95 58.19 90 bottom
C575  4.7uF  [C0402]  217.3 62.51 180 bottom
C576  22uF  [C0603]  219.58 60.99 0 bottom
C577  100uF  [C1210]  204.85 55.14 270 top
C578  100uF  [C1210]  208.53 60.48 90 top
C579  100uF  [C1210]  209.33 75.17 180 top
C580  100uF  [C1210]  210.82 42.19 90 top
C581  100uF  [C1210]  204.85 60.48 90 top
C582  100uF  [C1210]  209.36 78.71 180 top
C583  100uF  [C1210]  201.17 55.14 270 top
C584  470UF  [C7343H79]  195.83 57.43 270 top
C585  470UF  [C7343H79]  211.54 83.53 0 top
C586  100uF  [C1210]  215.39 44.35 180 top
C587  100uF  [C1210]  207.26 42.19 90 top
C588  100uF  [C1210]  208.53 55.14 270 top
C589  220UF  [C1206H71]  185.92 57.89 90 top
C590  220UF  [C1206H71]  195.12 83.34 0 top
C591  220UF  [C1206H71]  193.17 79.07 270 top
C592  470UF  [C7343H79]  196.09 40.67 270 top
C593  470UF  [C7343H79]  181.99 66.32 90 top
C594  470UF  [C7343H79]  195.24 88.91 180 top
C595  470UF  [C7343H79]  187.17 81.27 90 top
C596  470UF  [C7343H79]  202.44 40.67 270 top
C597  220UF  [C1206H71]  184.53 40.79 90 top
C598  220UF  [C1206H71]  187.45 40.79 90 top
C599  220UF  [C1206H71]  184.66 53.62 180 top
C600  470UF  [C7343H79]  180.09 40.67 270 top
C601  10uF  [C0402]  70.26 210.46 90 top
C602  4.7uF  [C0402]  68.35 220.52 180 bottom
C603  22UF  [C0805H60_SP]  70.36 219.2 270 bottom
C604  47uF  [C0805H60]  106.02 260.27 0 top
C605  0.1uF  [C0402]  22.56 75.39 0 top
C606  1uF  [C0402]  187.5 217.53 0 top
C607  0.22uF  [C0402]  200.3 258.78 0 bottom
C608  0.01uF  [C0402]  198.86 276.3 270 top
C609  100uF  [C0805H53]  217.39 101.17 180 top
C610  47uF  [C0805H60]  204.55 97.66 90 top
C611  47uF  [C0805H60]  201.88 97.66 90 top
C612  47uF  [C0805H60]  204.67 104.9 270 top
C613  47uF  [C0805H60]  201.88 104.9 270 top
C614  10UF  [C1206]  108.99 282.6 180 top
C615  100uF  [C0805H53]  109.58 265.02 270 top
C616  47uF  [C0805H60]  106.02 257.84 0 top
C617  10UF  [C1206]  234.71 101.93 90 top
C618  0.1uF  [C0201]  213.44 125.81 90 top
C619  0.1uF  [C0201]  169.65 222.3 0 bottom
C620  0.1uF  [C0201]  170.38 226.24 0 bottom
C621  0.1uF  [C0402]  165.74 40.06 180 top
C622  0.1uF  [C0402]  223.95 146.48 0 bottom
C623  0.1uF  [C0201]  200.04 97.49 0 top
C624  0.1uF  [C0201]  178.68 60.87 180 top
C625  0.1uF  [C0201]  194.83 85.33 180 top
C626  0.1uF  [C0201]  196.72 68.49 270 top
C627  0.1uF  [C0201]  181.83 78.75 180 top
C628  0.1uF  [C0201]  160.91 247.75 270 bottom
C629  0.1uF  [C0402]  166.18 116.47 160 top
C630  0.1uF  [C0201]  201.73 167.94 270 bottom
C631  0.1uF  [C0201]  179.78 55.12 90 top
C632  0.1uF  [C0201]  165.63 203.61 180 bottom
C633  0.1uF  [C0201]  229.64 168.33 180 top
C634  0.1uF  [C0201]  225.35 167.92 0 top
C635  0.1uF  [C0201]  166.14 216.92 0 bottom
C636  0.1uF  [C0201]  76.2 102.44 0 top
C637  0.1uF  [C0201]  71.55 84.53 270 top
C638  0.1uF  [C0201]  71.55 83.39 270 top
C639  1000pF  [C0402]  192.56 260.96 180 top
C640  1000pF  [C0402]  198.27 258.78 180 bottom
C641  68NF  [C0805H55]  229.87 102.92 90 bottom
C642  4.7NF  [C0402]  140.28 267.97 90 bottom
C643  68NF  [C0805H55]  138.51 268.55 90 bottom
C644  4.7NF  [C0402]  107.92 274.5 180 bottom
C645  68NF  [C0805H55]  107.29 276.28 180 bottom
C646  0.1uF  [C0201]  149.28 202.67 60 top
C647  0.1uF  [C0201]  174.07 176.53 0 top
C648  1uF  [C0603]  230.89 194.94 180 top
C649  1uF  [C0603]  230.71 198.53 180 top
C660  100pF  [C0201]  142.21 144.49 0 top
C661  1000pF  [C0201]  142.21 145.25 0 top
C662  0.1uF  [C0201]  142.21 146.01 0 top
C663  100pF  [C0201]  138.91 199.28 0 top
C664  1000pF  [C0201]  138.91 198.51 0 top
C665  0.1uF  [C0201]  138.91 197.75 0 top
C666  100pF  [C0201]  144.74 146.02 180 top
C667  1000pF  [C0201]  144.74 145.26 180 top
C668  0.1uF  [C0201]  144.74 144.5 180 top
C669  100pF  [C0201]  100.48 144.72 0 top
C670  1000pF  [C0201]  100.48 145.48 0 top
C671  0.1uF  [C0201]  100.48 146.24 0 top
C672  100pF  [C0201]  109.66 198.96 0 top
C673  1000pF  [C0201]  109.66 198.2 0 top
C674  0.1uF  [C0201]  109.66 197.43 0 top
C675  100pF  [C0201]  103 146.25 180 top
C676  1000pF  [C0201]  103 145.49 180 top
C677  0.1uF  [C0201]  103 144.73 180 top
C678  0.1uF  [C0201]  65.91 43.81 0 top
C679  0.1uF  [C0201]  48.21 81.69 0 top
C680  0.1uF  [C0201]  80.06 66.88 270 top
C681  0.1uF  [C0201]  80.06 65.48 270 top
C682  0.1uF  [C0201]  49.61 81.69 0 top
C683  0.1uF  [C0201]  67.31 43.81 0 top
C684  0.1uF  [C0201]  65.3 66.9 270 top
C685  0.1uF  [C0201]  79.98 83.95 270 top
C686  0.1uF  [C0201]  65.3 65.51 270 top
C687  0.1uF  [C0201]  79.98 82.55 270 top
C688  0.1uF  [C0201]  34.32 101.47 270 top
C689  0.1uF  [C0201]  19.46 101.47 270 top
C690  0.1uF  [C0201]  34.32 100.08 270 top
C691  0.1uF  [C0201]  92.2 32.64 270 bottom
C692  0.1uF  [C0201]  128.27 129.67 180 bottom
C693  0.1uF  [C0201]  128.27 127.38 180 bottom
C694  0.1uF  [C0201]  128.27 124.21 180 bottom
C695  0.1uF  [C0201]  116.23 129.74 0 bottom
C696  0.1uF  [C0201]  116.26 124.13 0 bottom
C697  0.1uF  [C0201]  116.33 127.33 0 bottom
C698  0.1uF  [C0201]  111.38 124.21 180 bottom
C699  0.1uF  [C0201]  111.38 124.97 180 bottom
C700  0.1uF  [C0201]  111.38 121.79 180 bottom
C701  0.1uF  [C0201]  111.48 128.09 180 bottom
C702  0.1uF  [C0201]  111.4 127.33 180 bottom
C703  0.1uF  [C0201]  129.03 126.49 0 bottom
C704  180UF  [CPLSMSQ327H472]  221.54 244.91 180 top
C705  180UF  [CPLSMSQ327H472]  221.62 235.66 180 top
C706  0.1uF  [C0201]  226.8 123.52 0 top
C707  1uF  [C0402]  141.71 244.88 90 top
C708  1uF  [C0402]  101.83 256.64 270 top
C709  0.1uF  [C0201]  187.05 215.87 90 top
C710  0.1uF  [C0201]  216.08 132.41 270 top
C711  0.1uF  [C0201]  187.78 218.49 180 top
C712  0.1uF  [C0201]  188.14 226.06 90 top
C713  0.1uF  [C0201]  145.39 245.21 270 top
C714  0.1uF  [C0201]  207.57 143.05 270 bottom
C715  0.1uF  [C0201]  211.43 126.19 180 top
C716  0.1uF  [C0201]  211.48 125.43 180 top
C717  0.1uF  [C0201]  211.4 124.61 180 top
C718  0.1uF  [C0201]  207.77 123.44 270 top
C719  0.1uF  [C0201]  226.62 134.72 0 bottom
C720  0.1uF  [C0201]  205.87 126.14 180 top
C721  0.1uF  [C0201]  205.94 125.35 180 top
C722  0.1uF  [C0201]  205.97 124.59 180 top
C723  0.1uF  [C0201]  201.47 123.42 270 top
C748  0.1uF  [C0201]  15.95 231.47 90 bottom
C749  0.1uF  [C0201]  84.61 227.38 180 bottom
C750  47UF  [C0603]  116.15 173.15 180 bottom
C751  47UF  [C0603]  126.42 166.32 90 bottom
C752  47UF  [C0603]  131.8 173.41 0 bottom
C753  1uF  [C0402]  167.18 262.36 90 top
C754  47uF  [C0805H60]  164.44 269.44 0 top
C755  47uF  [C0805H60]  168.5 269.57 0 top
C756  47uF  [C0805H60]  172.82 269.44 0 top
C757  22UF  [C1210H106]  162.28 257.51 0 bottom
C758  22UF  [C1210H106]  168.38 257.51 0 bottom
C759  22UF  [C1210H106]  174.47 257.51 0 bottom
C760  0.1uF  [C0402]  217.04 191.16 0 bottom
C761  0.1uF  [C0402]  225.04 193.8 270 bottom
C762  0.1uF  [C0402]  224.41 192.84 0 top
C763  1uF  [C0402]  144.5 244.17 90 top
C764  1uF  [C0402]  171.78 262.89 90 top
C765  0.1uF  [C0201]  56.49 237.77 270 bottom
C766  0.1uF  [C0201]  60.96 238.15 270 bottom
C771  1uF  [C0402H22]  33.17 205.82 270 bottom
C772  1uF  [C0402H22]  34.26 205.79 270 bottom
C773  1uF  [C0402#2]  31.06 200.53 0 top
C774  1uF  [C0402#2]  31.06 197.54 0 top
C775  1uF  [C0402#2]  32.44 201.9 270 top
C776  1uF  [C0402#2]  30.96 199.03 0 top
C777  1uF  [C0402#2]  36.98 202.03 180 top
C778  1uF  [C0402#2]  36.53 199.03 180 top
C779  1uF  [C0402#2]  31.09 201.52 0 top
C780  1uF  [C0402#2]  35.43 201.98 270 top
C781  1uF  [C0402#2]  36.5 200.53 180 top
C782  1uF  [C0402#2]  36.5 197.51 180 top
C783  1uF  [C0402#2]  34.29 202.06 270 top
C784  1uF  [C0402#2]  35.59 196.32 90 top
C785  1uF  [C0402#2]  33.07 196.55 90 top
C786  1uF  [C0402#2]  31.14 196.21 90 top
C845  4.7uF  [C0805H53]  91.11 282.85 180 bottom
C847  0.1uF  [C0402#2]  94.13 277.93 90 top
C852  1uF  [C0402#2]  87.1 256.31 270 bottom
C853  100uF  [C0805H53]  88.49 268.91 0 bottom
C854  1uF  [C0402#2]  87.78 263.73 90 bottom
C855  10uF  [C0402#2]  90.07 260.5 270 bottom
C856  4.7uF  [C0805H53]  84.23 268.88 180 bottom
C857  1uF  [C0402#2]  86.92 264.54 90 bottom
C858  2.2uF  [C0402H22#2]  92.96 259.44 270 bottom
C859  22UF  [C0805H55]  84.38 258.57 90 bottom
C864  4.7uF  [C0402]  92.84 257.58 90 bottom
CLK  85305-0232  [CNSMASQ197H161]  121.41 207.67 180 bottom
CLK_A  85305-0232  [CNSMASQ197H161]  59.94 195 225 bottom
CLK_B  85305-0232  [CNSMASQ197H161]  181.81 195.4 135 bottom
D1  1N4148W-7-F  [SOD123-2]  226.75 223.6 270 top
D2  SMAJ14A  [DO214AC_A]  218.34 260.96 0 top
D3  CDBU0520-HF  [SOD523FH33]  223.29 255.88 90 top
D4  MBRA340T3G  [SMA]  211.48 256.13 270 top
D5  TS4148C RZG  [D0603H33]  200.8 254.53 270 bottom
D6  BZX84-C13V  [SOT23]  198.27 255.88 0 top
DACA0  SF1521-60070-1S  [CNAMPHENOLSF1521-60070-XS]  62.33 157.24 60 top
DACA1  SF1521-60070-1S  [CNAMPHENOLSF1521-60070-XS]  55.09 138.78 80 top
DACA2  SF1521-60070-1S  [CNAMPHENOLSF1521-60070-XS]  54.7 118.95 100 top
DACA3  SF1521-60070-1S  [CNAMPHENOLSF1521-60070-XS]  61.15 100.19 120 top
DACB0  SF1521-60070-1S  [CNAMPHENOLSF1521-60070-XS]  183.71 155.25 300 top
DACB1  SF1521-60070-1S  [CNAMPHENOLSF1521-60070-XS]  190.03 136.47 280 top
DACB2  SF1521-60070-1S  [CNAMPHENOLSF1521-60070-XS]  189.62 116.61 260 top
DACB3  SF1521-60070-1S  [CNAMPHENOLSF1521-60070-XS]  182.47 98.12 240 top
DS1  APHHS1005LSYCK/J3-PF  [LED0402H24]  24.16 216.18 180 top
DS2  APHHS1005LSYCK/J3-PF  [LED0402H24]  100.38 200.05 270 top
DS3  APHHS1005LCGCK  [LED0402_A]  234.8 267 180 top
DS4  APHHS1005LCGCK  [LED0402_A]  234.72 256.15 180 top
DS5  APHHS1005LCGCK  [LED0402_A]  234.72 262.56 180 top
DS6  APHHS1005LCGCK  [LED0402_A]  234.78 234.12 180 top
DS7  APHHS1005LCGCK  [LED0402_A]  234.78 232.72 180 top
DS8  APHHS1005LCGCK  [LED0402_A]  234.76 238.87 180 top
DS9  APHHS1005LCGCK  [LED0402_A]  234.76 240.26 180 top
DS10  APHHS1005LCGCK  [LED0402_A]  234.73 246.31 180 top
DS11  APHHS1005LCGCK  [LED0402_A]  234.78 252.1 180 top
DS12  APHHS1005LCGCK  [LED0402_A]  234.78 250.7 180 top
DS13  APHHS1005LCGCK  [LED0402_A]  234.72 257.54 180 top
DS14  APHHS1005LCGCK  [LED0402_A]  234.73 244.91 180 top
DS15  APHHS1005LCGCK  [LED0402_A]  234.72 263.96 180 top
DS16  APHHS1005LCGCK  [LED0402_A]  196.01 264.9 270 top
DS17  APHHS1005LCGCK  [LED0402_A]  208.64 113.11 90 top
DS18  APHHS1005LSECK/J3-PF  [LED0402H24]  5.16 72.85 0 top
DS19  APHHS1005LSECK/J3-PF  [LED0402H24]  5.15 74.37 0 top
